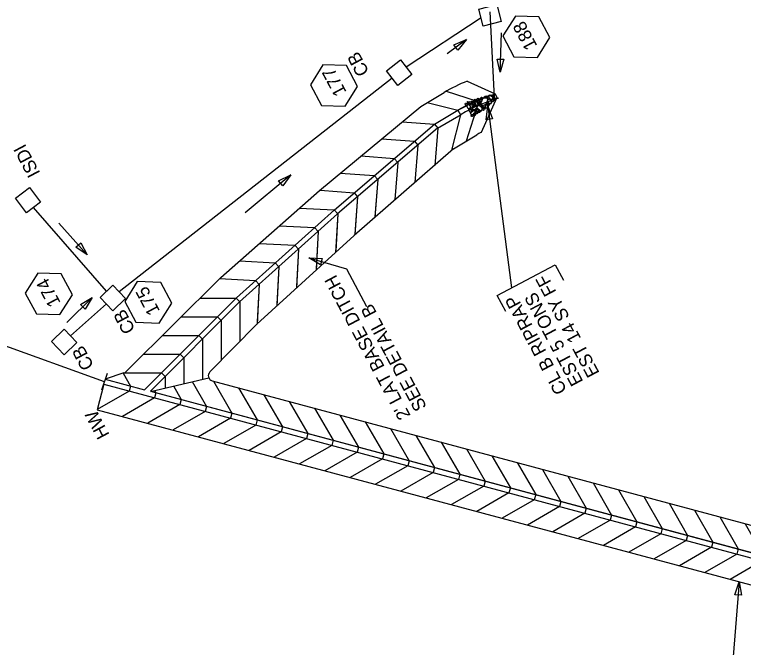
# Model space of a CAD drawing. Extents: x 2384780 to 2405432, y 547869 to 573706.
# Drawn here: x 2401953.5 to 2402230.7, y 571206.6 to 571447.5 of the extents above; entities that cross this region are included whole.
import ezdxf

# ---------------------------------------------------------------- set-up
doc = ezdxf.new("R2010")
doc.units = 0
for name, color, linetype in [('Old_Level_1', 7, 'Continuous'), ('Old_Level_18', 7, 'Continuous'), ('Old_Level_20', 7, 'Continuous'), ('Old_Level_5', 7, 'Continuous'), ('Old_Level_9', 7, 'Continuous'), ('Prop Drainage Structure Pipe RCP 36in', 7, 'Continuous')]:
    doc.layers.add(name, color=color, linetype=linetype)

# ---------------------------------------------------------------- blocks, each defined once
blk = doc.blocks.new('HDWL')
at = {"layer": 'Old_Level_1'}
for p, q in [((0, -0.0655), (0, 0.0685)), ((0, 0), (-0.0685, 0))]:
    blk.add_line(p, q, dxfattribs=at)

msp = doc.modelspace()

# ---------------------------------------------------------------- linework, layer by layer
at = {"layer": 'Old_Level_1'}
for p, q in [((2402136, 571416), (2402134.37, 571448.61)), ((2402130.92, 571446.33), (2402102.38, 571427.47)), ((2402097.07, 571423.39), (2401993.28, 571341.97)), ((2401988.43, 571342.2), (2401960.71, 571374.05)), ((2401988.46, 571337.38), (2401974.78, 571325.22)), ((2401994.99, 571311.1), (2401987.96, 571308.73)), ((2402005.13, 571304.12), (2402027.3, 571309.3)), ((2401987.44, 571306.8), (2401984.85, 571297.14))]:
    msp.add_line(p, q, dxfattribs=at)
for points in [[(2402131.92, 571415.92), (2402132.03, 571416.2), (2402132.4, 571416.54), (2402132.69, 571416.48), (2402132.79, 571416.28), (2402132.34, 571415.81), (2402132.11, 571415.81), (2402131.92, 571415.92)], [(2402132.65, 571415.95), (2402132.69, 571416.23), (2402133.07, 571416.57), (2402133.37, 571416.47), (2402133.46, 571416.31), (2402133.04, 571415.83), (2402132.8, 571415.82), (2402132.65, 571415.95)], [(2402133.61, 571416.29), (2402133.73, 571416.1), (2402133.95, 571415.71), (2402133.74, 571415.45), (2402133.58, 571415.37), (2402133.28, 571415.89), (2402133.33, 571416.26), (2402133.61, 571416.29)], [(2402134.24, 571417.02), (2402134.59, 571416.76), (2402135.34, 571416.05), (2402135.17, 571415.35), (2402134.68, 571415.13), (2402133.85, 571416.03), (2402133.83, 571416.68), (2402134.13, 571416.96)], [(2402135.68, 571415.94), (2402135.51, 571416.1), (2402135.07, 571416.42), (2402135.23, 571416.73), (2402135.4, 571416.82), (2402135.93, 571416.42), (2402135.94, 571416.09), (2402135.68, 571415.94)], [(2402125.16, 571413.86), (2402125.38, 571413.64), (2402125.65, 571413.23), (2402125.41, 571412.98), (2402125.14, 571412.91), (2402124.9, 571413.5), (2402124.98, 571413.8), (2402125.16, 571413.86)], [(2402126.12, 571413.62), (2402126.44, 571413.21), (2402126.94, 571412.38), (2402126.49, 571411.73), (2402125.96, 571411.69), (2402125.44, 571412.77), (2402125.66, 571413.37), (2402126.12, 571413.62)], [(2402125.97, 571414.48), (2402126.18, 571414.25), (2402126.46, 571413.85), (2402126.21, 571413.59), (2402125.95, 571413.52), (2402125.71, 571414.11), (2402125.79, 571414.41), (2402125.97, 571414.48)], [(2402126.65, 571414.49), (2402126.88, 571414.27), (2402127.16, 571413.86), (2402126.91, 571413.61), (2402126.65, 571413.54), (2402126.41, 571414.13), (2402126.49, 571414.43), (2402126.65, 571414.49)], [(2402127.07, 571414.07), (2402127.21, 571414.37), (2402127.57, 571414.73), (2402127.84, 571414.62), (2402127.92, 571414.47), (2402127.51, 571413.97), (2402127.26, 571413.96), (2402127.07, 571414.07)], [(2402127.38, 571413.43), (2402127.52, 571413.59), (2402127.85, 571414), (2402128.2, 571413.85), (2402128.28, 571413.68), (2402127.83, 571413.18), (2402127.59, 571413.29), (2402127.38, 571413.43)], [(2402128.44, 571413.8), (2402128.27, 571413.95), (2402127.94, 571414.33), (2402128.03, 571414.62), (2402128.15, 571414.7), (2402128.59, 571414.39), (2402128.63, 571414.07), (2402128.52, 571413.88)], [(2402128, 571412.97), (2402128.08, 571413.28), (2402128.45, 571413.61), (2402128.76, 571413.51), (2402128.82, 571413.33), (2402128.42, 571412.89), (2402128.19, 571412.85), (2402128, 571412.97)], [(2402128.29, 571414.72), (2402128.34, 571415), (2402128.71, 571415.34), (2402129.01, 571415.25), (2402129.1, 571415.08), (2402128.69, 571414.6), (2402128.44, 571414.59), (2402128.29, 571414.72)], [(2402129.33, 571414.88), (2402129.68, 571414.47), (2402130.09, 571413.54), (2402129.71, 571412.98), (2402129.17, 571412.88), (2402128.67, 571413.97), (2402128.85, 571414.68), (2402129.33, 571414.88)], [(2402129.28, 571415.04), (2402129.33, 571415.32), (2402129.7, 571415.66), (2402130, 571415.56), (2402130.09, 571415.4), (2402129.69, 571414.91), (2402129.43, 571414.9), (2402129.28, 571415.04)], [(2402130.18, 571414.21), (2402129.98, 571414.35), (2402129.57, 571414.68), (2402129.76, 571415.01), (2402129.9, 571415.08), (2402130.4, 571414.67), (2402130.4, 571414.45), (2402130.18, 571414.21)], [(2402130.13, 571413.78), (2402130.17, 571414.05), (2402130.57, 571414.36), (2402130.85, 571414.31), (2402130.96, 571414.12), (2402130.54, 571413.65), (2402130.29, 571413.65), (2402130.13, 571413.78)], [(2402130.39, 571415.63), (2402130.73, 571415.48), (2402131.23, 571414.98), (2402131.13, 571414.54), (2402130.86, 571414.4), (2402130.19, 571414.97), (2402130.18, 571415.4), (2402130.39, 571415.63)], [(2402130.65, 571413.49), (2402130.91, 571413.28), (2402131.01, 571412.87), (2402130.81, 571412.53), (2402130.59, 571412.55), (2402130.3, 571413.07), (2402130.49, 571413.4), (2402130.65, 571413.49)], [(2402131.1, 571416.14), (2402131.31, 571415.92), (2402131.59, 571415.51), (2402131.34, 571415.25), (2402131.08, 571415.19), (2402130.84, 571415.78), (2402130.92, 571416.08), (2402131.1, 571416.14)], [(2402130.91, 571413.31), (2402130.99, 571414.16), (2402131.72, 571415.74), (2402132.93, 571415.81), (2402133.52, 571415.24), (2402132.66, 571413.25), (2402131.75, 571412.88), (2402130.85, 571413.15)], [(2402132.93, 571413.86), (2402132.98, 571414.14), (2402133.36, 571414.47), (2402133.66, 571414.41), (2402133.72, 571414.22), (2402133.32, 571413.77), (2402133.12, 571413.75), (2402132.93, 571413.86)], [(2402132.96, 571413.27), (2402133.06, 571413.58), (2402133.44, 571413.86), (2402133.73, 571413.82), (2402133.84, 571413.62), (2402133.37, 571413.15), (2402133.15, 571413.16), (2402132.96, 571413.27)], [(2402134.05, 571415.51), (2402134.39, 571415.14), (2402134.89, 571414.25), (2402134.46, 571413.62), (2402134.01, 571413.59), (2402133.48, 571414.7), (2402133.65, 571415.26), (2402134.05, 571415.51)], [(2402134.71, 571414.64), (2402134.89, 571414.95), (2402135.3, 571415.43), (2402135.83, 571415.33), (2402136.03, 571414.99), (2402135.34, 571414.38), (2402134.98, 571414.4), (2402134.71, 571414.64)], [(2402136.28, 571415.12), (2402136.1, 571415.28), (2402135.64, 571415.63), (2402135.84, 571415.9), (2402136, 571416), (2402136.48, 571415.62), (2402136.54, 571415.27), (2402136.28, 571415.12)], [(2402126.72, 571411.72), (2402126.96, 571411.44), (2402127.27, 571410.88), (2402126.91, 571410.45), (2402126.62, 571410.38), (2402126.25, 571411.25), (2402126.41, 571411.6), (2402126.72, 571411.72)], [(2402127.46, 571412.14), (2402127.14, 571412.35), (2402126.68, 571412.92), (2402126.81, 571413.32), (2402127.07, 571413.46), (2402127.66, 571412.86), (2402127.75, 571412.48), (2402127.46, 571412.14)], [(2402128.63, 571410.61), (2402128.42, 571410.15), (2402127.71, 571409.4), (2402127.02, 571409.57), (2402126.87, 571410.09), (2402127.76, 571410.94), (2402128.25, 571410.99), (2402128.7, 571410.65)], [(2402127.16, 571410.95), (2402127.22, 571411.24), (2402127.59, 571411.59), (2402127.89, 571411.49), (2402127.98, 571411.33), (2402127.56, 571410.84), (2402127.32, 571410.82), (2402127.16, 571410.95)], [(2402129.36, 571412.43), (2402129.1, 571412.08), (2402128.35, 571411.32), (2402127.7, 571411.51), (2402127.44, 571411.96), (2402128.36, 571412.78), (2402128.96, 571412.94), (2402129.28, 571412.51)], [(2402128.7, 571411.2), (2402128.75, 571411.44), (2402129.15, 571411.85), (2402129.45, 571411.76), (2402129.51, 571411.57), (2402129.1, 571411.09), (2402128.9, 571411.06), (2402128.7, 571411.2)], [(2402129.6, 571411.44), (2402129.86, 571411.24), (2402129.96, 571410.82), (2402129.76, 571410.49), (2402129.54, 571410.5), (2402129.25, 571411.02), (2402129.44, 571411.35), (2402129.6, 571411.44)], [(2402130.72, 571410.93), (2402130.26, 571411.21), (2402129.33, 571411.95), (2402129.65, 571412.85), (2402130.07, 571413.09), (2402131.13, 571412.06), (2402131.22, 571411.3), (2402130.79, 571410.83)], [(2402129.86, 571410.3), (2402129.9, 571410.59), (2402130.28, 571410.92), (2402130.58, 571410.86), (2402130.64, 571410.67), (2402130.25, 571410.23), (2402130.06, 571410.2), (2402129.86, 571410.3)], [(2402131.23, 571412.19), (2402131.3, 571412.46), (2402131.68, 571412.76), (2402131.98, 571412.7), (2402132.08, 571412.51), (2402131.64, 571412.07), (2402131.42, 571412.08), (2402131.23, 571412.19)], [(2402131.85, 571411.08), (2402131.6, 571411.16), (2402131.29, 571411.46), (2402131.32, 571411.81), (2402131.6, 571411.98), (2402131.96, 571411.49), (2402132.01, 571411.18), (2402131.85, 571411.08)], [(2402131.85, 571411.66), (2402131.91, 571411.95), (2402132.29, 571412.28), (2402132.58, 571412.2), (2402132.64, 571412.02), (2402132.25, 571411.58), (2402132.05, 571411.55), (2402131.85, 571411.66)], [(2402132.95, 571413.24), (2402133.25, 571412.94), (2402133.54, 571412.42), (2402133.2, 571411.97), (2402132.86, 571411.95), (2402132.52, 571412.75), (2402132.7, 571413.1), (2402132.95, 571413.24)], [(2402133.36, 571412.83), (2402133.4, 571413.12), (2402133.78, 571413.45), (2402134.09, 571413.37), (2402134.14, 571413.19), (2402133.74, 571412.75), (2402133.54, 571412.71), (2402133.36, 571412.83)], [(2402127.14, 571408.84), (2402127.18, 571409.13), (2402127.56, 571409.46), (2402127.87, 571409.39), (2402127.92, 571409.2), (2402127.54, 571408.76), (2402127.33, 571408.73), (2402127.14, 571408.84)], [(2402128.44, 571410.09), (2402128.68, 571409.88), (2402128.79, 571409.46), (2402128.58, 571409.14), (2402128.36, 571409.15), (2402128.07, 571409.68), (2402128.28, 571410), (2402128.44, 571410.09)], [(2402129.46, 571409.74), (2402129.14, 571409.86), (2402128.86, 571410.21), (2402128.88, 571410.53), (2402129.14, 571410.69), (2402129.5, 571410.2), (2402129.59, 571409.9), (2402129.46, 571409.74)]]:
    msp.add_lwpolyline(points, dxfattribs=at)
for points in [[(2401990.85, 571334.8), (2401986.01, 571339.9), (2401990.86, 571344.51), (2401995.7, 571339.42)], [(2401972.35, 571318.06), (2401967.51, 571323.15), (2401972.36, 571327.76), (2401977.2, 571322.67)]]:
    msp.add_lwpolyline(points, close=True, dxfattribs=at)
at = {"layer": 'Old_Level_18'}
for p, q in [((2402107.93, 571412.59), (2402116.83, 571417.88)), ((2402113.16, 571405.83), (2402122.05, 571411.11)), ((2402114.38, 571404.24), (2402123.28, 571409.53)), ((2402120.38, 571396.47), (2402129.28, 571401.75)), ((2401995.44, 571311.15), (2401996.13, 571311.95)), ((2401987.96, 571308.73), (2402002.89, 571304.72)), ((2402028.63, 571308.17), (2402317.94, 571230.51)), ((2401987.44, 571306.8), (2402324.49, 571216.33)), ((2402005.1, 571304.13), (2402325, 571218.26)), ((2401984.85, 571297.14), (2402312.23, 571209.27))]:
    msp.add_line(p, q, dxfattribs=at)
for points in [[(2402117.58, 571418.32), (2402128.98, 571414.7), (2402128.98, 571414.7), (2402128.98, 571414.7), (2402129.7, 571413.31), (2402125.28, 571399.38)], [(2402122.05, 571411.11), (2402128.26, 571414.33), (2402134.79, 571416.81), (2402136.36, 571417.28)], [(2402110.42, 571414.07), (2402122.05, 571411.11), (2402122.05, 571411.11), (2402122.05, 571411.11), (2402123.11, 571409.33), (2402119.68, 571395.86)], [(2401996.13, 571311.95), (2402031.85, 571347.5), (2402069.49, 571380.57), (2402107.93, 571412.59)], [(2402113.16, 571405.83), (2402122.05, 571411.11)], [(2402002.89, 571304.72), (2402037.85, 571339.73), (2402075.12, 571373.27), (2402113.16, 571405.83)], [(2402100.94, 571406.77), (2402113.16, 571405.83), (2402113.16, 571405.83), (2402113.16, 571405.83), (2402114.46, 571404.3), (2402113.36, 571390.14)], [(2402114.38, 571404.24), (2402076.34, 571371.69), (2402039.07, 571338.14), (2402005.1, 571304.13)], [(2402093.12, 571400.26), (2402105.53, 571399.3), (2402105.53, 571399.3), (2402105.53, 571399.3), (2402106.83, 571397.77), (2402105.74, 571383.61)], [(2402120.38, 571396.47), (2402082.67, 571363.5), (2402045.64, 571329.64), (2402027.73, 571311.5)], [(2402085.3, 571393.74), (2402097.9, 571392.77), (2402097.9, 571392.77), (2402097.9, 571392.77), (2402099.21, 571391.24), (2402098.11, 571377.08)], [(2402077.48, 571387.23), (2402090.27, 571386.24), (2402090.27, 571386.24), (2402090.27, 571386.24), (2402091.58, 571384.71), (2402090.46, 571370.31)], [(2402077.48, 571387.23), (2402090.27, 571386.24), (2402090.27, 571386.24), (2402090.27, 571386.24), (2402091.58, 571384.71), (2402090.48, 571370.55)], [(2402069.66, 571380.71), (2402082.64, 571379.71), (2402082.64, 571379.71), (2402082.64, 571379.71), (2402083.95, 571378.18), (2402082.82, 571363.64)], [(2402069.66, 571380.71), (2402082.64, 571379.71), (2402082.64, 571379.71), (2402082.64, 571379.71), (2402083.95, 571378.18), (2402082.85, 571364.02)], [(2402061.86, 571373.87), (2402075.02, 571373.18), (2402075.02, 571373.18), (2402075.02, 571373.18), (2402076.36, 571371.68), (2402075.59, 571357.02)], [(2402061.86, 571373.87), (2402075.02, 571373.18), (2402075.02, 571373.18), (2402075.02, 571373.18), (2402076.36, 571371.68), (2402075.61, 571357.5)], [(2402054.23, 571367.16), (2402067.55, 571366.46), (2402067.55, 571366.46), (2402067.55, 571366.46), (2402068.9, 571364.96), (2402068.12, 571350.19)], [(2402054.23, 571367.16), (2402067.55, 571366.46), (2402067.55, 571366.46), (2402067.55, 571366.46), (2402068.9, 571364.96), (2402068.15, 571350.78)], [(2402046.59, 571360.45), (2402060.09, 571359.74), (2402060.09, 571359.74), (2402060.09, 571359.74), (2402061.43, 571358.25), (2402060.65, 571343.36)], [(2402046.59, 571360.45), (2402060.09, 571359.74), (2402060.09, 571359.74), (2402060.09, 571359.74), (2402061.43, 571358.25), (2402060.69, 571344.06)], [(2402038.96, 571353.74), (2402052.62, 571353.02), (2402052.62, 571353.02), (2402052.62, 571353.02), (2402053.97, 571351.53), (2402053.18, 571336.53)], [(2402038.96, 571353.74), (2402052.62, 571353.02), (2402052.62, 571353.02), (2402052.62, 571353.02), (2402053.97, 571351.53), (2402053.22, 571337.35)], [(2402031.38, 571347.03), (2402045.16, 571346.31), (2402045.16, 571346.31), (2402045.16, 571346.31), (2402046.51, 571344.81), (2402045.71, 571329.71)], [(2402031.38, 571347.03), (2402045.16, 571346.31), (2402045.16, 571346.31), (2402045.16, 571346.31), (2402046.51, 571344.81), (2402045.76, 571330.63)], [(2402023.89, 571339.57), (2402037.71, 571339.58), (2402037.71, 571339.58), (2402037.71, 571339.58), (2402039.13, 571338.16), (2402039.14, 571323.05)], [(2402023.89, 571339.57), (2402037.71, 571339.58), (2402037.71, 571339.58), (2402037.71, 571339.58), (2402039.13, 571338.16), (2402039.14, 571323.96)], [(2402016.75, 571332.47), (2402030.61, 571332.48), (2402030.61, 571332.48), (2402030.61, 571332.48), (2402032.03, 571331.05), (2402032.04, 571315.87)], [(2402016.75, 571332.47), (2402030.61, 571332.48), (2402030.61, 571332.48), (2402030.61, 571332.48), (2402032.03, 571331.05), (2402032.04, 571316.85)], [(2402009.61, 571325.36), (2402023.51, 571325.37), (2402023.51, 571325.37), (2402023.51, 571325.37), (2402024.94, 571323.95), (2402024.94, 571308.68)], [(2402009.61, 571325.36), (2402023.51, 571325.37), (2402023.51, 571325.37), (2402023.51, 571325.37), (2402024.94, 571323.95), (2402024.94, 571309.75)], [(2402002.47, 571318.26), (2402016.42, 571318.27), (2402016.42, 571318.27), (2402016.42, 571318.27), (2402017.84, 571316.85), (2402017.85, 571307.09)], [(2401994.77, 571311.03), (2401997.59, 571306.14), (2401997.59, 571306.14), (2401997.59, 571306.14), (2401997.07, 571304.22), (2401984.85, 571297.17)], [(2401995.12, 571311.15), (2402009.32, 571311.16), (2402009.32, 571311.16), (2402009.32, 571311.16), (2402010.74, 571309.74), (2402010.75, 571305.43)], [(2401987.96, 571308.73), (2402002.89, 571304.72)], [(2402013.86, 571306.16), (2402016.85, 571300.97), (2402016.85, 571300.97), (2402016.85, 571300.97), (2402016.33, 571299.05), (2402004.11, 571292)], [(2402021.03, 571307.84), (2402026.48, 571298.39), (2402026.48, 571298.39), (2402026.48, 571298.39), (2402025.96, 571296.46), (2402013.74, 571289.42)], [(2402029.06, 571308.02), (2402036.11, 571295.81), (2402036.11, 571295.81), (2402036.11, 571295.81), (2402035.59, 571293.88), (2402023.37, 571286.83)], [(2402038.69, 571305.44), (2402045.74, 571293.22), (2402045.74, 571293.22), (2402045.74, 571293.22), (2402045.22, 571291.29), (2402033, 571284.25)], [(2402006.68, 571304.48), (2402007.22, 571303.56), (2402007.22, 571303.56), (2402007.22, 571303.56), (2402006.7, 571301.63), (2401994.48, 571294.59)], [(2402005.1, 571304.13), (2402325, 571218.26)], [(2402048.32, 571302.85), (2402055.37, 571290.64), (2402055.37, 571290.64), (2402055.37, 571290.64), (2402054.85, 571288.71), (2402042.63, 571281.66)], [(2402057.95, 571300.27), (2402065, 571288.05), (2402065, 571288.05), (2402065, 571288.05), (2402064.48, 571286.12), (2402052.26, 571279.08)], [(2402067.58, 571297.68), (2402074.63, 571285.47), (2402074.63, 571285.47), (2402074.63, 571285.47), (2402074.11, 571283.54), (2402061.89, 571276.49)], [(2402077.21, 571295.1), (2402084.26, 571282.88), (2402084.26, 571282.88), (2402084.26, 571282.88), (2402083.74, 571280.95), (2402071.52, 571273.91)], [(2402086.84, 571292.51), (2402093.89, 571280.3), (2402093.89, 571280.3), (2402093.89, 571280.3), (2402093.37, 571278.37), (2402081.15, 571271.32)], [(2402096.47, 571289.93), (2402103.52, 571277.71), (2402103.52, 571277.71), (2402103.52, 571277.71), (2402103, 571275.78), (2402090.78, 571268.74)], [(2402106.1, 571287.34), (2402113.15, 571275.13), (2402113.15, 571275.13), (2402113.15, 571275.13), (2402112.63, 571273.2), (2402100.41, 571266.15)], [(2402115.73, 571284.76), (2402122.78, 571272.54), (2402122.78, 571272.54), (2402122.78, 571272.54), (2402122.26, 571270.61), (2402110.04, 571263.57)], [(2402125.36, 571282.17), (2402132.41, 571269.96), (2402132.41, 571269.96), (2402132.41, 571269.96), (2402131.89, 571268.03), (2402119.67, 571260.98)], [(2402134.99, 571279.59), (2402142.04, 571267.37), (2402142.04, 571267.37), (2402142.04, 571267.37), (2402141.52, 571265.44), (2402129.3, 571258.4)], [(2402144.62, 571277), (2402151.67, 571264.79), (2402151.67, 571264.79), (2402151.67, 571264.79), (2402151.15, 571262.86), (2402138.93, 571255.81)], [(2402154.25, 571274.42), (2402161.3, 571262.2), (2402161.3, 571262.2), (2402161.3, 571262.2), (2402160.78, 571260.28), (2402148.56, 571253.23)], [(2402163.88, 571271.83), (2402170.93, 571259.62), (2402170.93, 571259.62), (2402170.93, 571259.62), (2402170.41, 571257.69), (2402158.19, 571250.65)], [(2402173.51, 571269.25), (2402180.56, 571257.03), (2402180.56, 571257.03), (2402180.56, 571257.03), (2402180.04, 571255.11), (2402167.82, 571248.06)], [(2402183.14, 571266.66), (2402190.19, 571254.45), (2402190.19, 571254.45), (2402190.19, 571254.45), (2402189.67, 571252.52), (2402177.45, 571245.48)], [(2402192.77, 571264.08), (2402199.82, 571251.86), (2402199.82, 571251.86), (2402199.82, 571251.86), (2402199.3, 571249.94), (2402187.08, 571242.89)], [(2402202.4, 571261.49), (2402209.45, 571249.28), (2402209.45, 571249.28), (2402209.45, 571249.28), (2402208.93, 571247.35), (2402196.71, 571240.31)], [(2402212.03, 571258.91), (2402219.08, 571246.7), (2402219.08, 571246.7), (2402219.08, 571246.7), (2402218.56, 571244.77), (2402206.34, 571237.72)], [(2402221.66, 571256.33), (2402228.71, 571244.11), (2402228.71, 571244.11), (2402228.71, 571244.11), (2402228.19, 571242.18), (2402215.97, 571235.14)], [(2402231.29, 571253.74), (2402238.34, 571241.53), (2402238.34, 571241.53), (2402238.34, 571241.53), (2402237.82, 571239.6), (2402225.6, 571232.55)]]:
    msp.add_lwpolyline(points, dxfattribs=at)
for centre, radius, start, end in [((2402147.86, 571365.62), 60.78, 111.4459, 120.7011), ((2402153.08, 571358.85), 60.78, 105.9762, 120.7011), ((2402154.31, 571357.27), 60.78, 105.9762, 120.7011), ((2402160.31, 571349.5), 60.78, 118.9043, 120.7011), ((2402029.15, 571310.1), 2, 135.3618, 254.9754)]:
    msp.add_arc(centre, radius, start, end, dxfattribs=at)
at = {"layer": 'Old_Level_20'}
for points in [[(2402143.95, 571446.99), (2402139.21, 571439.4), (2402143.41, 571431.5), (2402152.36, 571431.19), (2402157.1, 571438.78), (2402152.9, 571446.68)], [(2402070.74, 571428.41), (2402066, 571420.82), (2402070.2, 571412.92), (2402079.15, 571412.61), (2402083.89, 571420.2), (2402079.69, 571428.1)]]:
    msp.add_lwpolyline(points, close=True, dxfattribs=at)
at = {"layer": 'Old_Level_5'}
for p, q in [((2402138.19, 571425.58), (2402138.63, 571440.6)), ((2402125.32, 571438.05), (2402118.01, 571432.53)), ((2402133.42, 571412.65), (2402142.46, 571343.49)), ((2402058.48, 571386.55), (2402041.21, 571372.04)), ((2401981.02, 571356.12), (2401970.28, 571368.13)), ((2402065.37, 571354.93), (2402079.65, 571350.81)), ((2402079.65, 571350.81), (2402087.31, 571336.42)), ((2401983.01, 571339.79), (2401973.33, 571330.29)), ((2402229.06, 571231.59), (2402224.52, 571175.91))]:
    msp.add_line(p, q, dxfattribs=at)
for points in [[(2402120.57, 571436.03), (2402125.32, 571438.05), (2402122.08, 571434.04)], [(2402139.58, 571430.54), (2402138.19, 571425.58), (2402137.08, 571430.62)], [(2402132.82, 571407.53), (2402133.42, 571412.65), (2402135.3, 571407.85)], [(2402053.85, 571384.29), (2402058.48, 571386.55), (2402055.45, 571382.38)], [(2401978.62, 571360.68), (2401981.02, 571356.12), (2401976.75, 571359.01)], [(2402069.77, 571352.25), (2402065.37, 571354.93), (2402070.51, 571354.63)], [(2401962.29, 571349.13), (2401957.54, 571341.54), (2401961.74, 571333.64), (2401970.69, 571333.32), (2401975.43, 571340.91), (2401971.23, 571348.81)], [(2402000.08, 571345.92), (2401995.34, 571338.33), (2401999.54, 571330.43), (2402008.48, 571330.12), (2402013.23, 571337.71), (2402009.03, 571345.61)], [(2401978.56, 571337.18), (2401983.01, 571339.79), (2401980.31, 571335.39)], [(2402227.4, 571226.71), (2402229.06, 571231.59), (2402229.9, 571226.51)]]:
    msp.add_lwpolyline(points, close=True, dxfattribs=at)
for points in [[(2402125.64, 571422.19), (2402136.32, 571417.39), (2402136.32, 571417.39), (2402136.32, 571417.39), (2402136.87, 571415.93), (2402130.93, 571402.7)], [(2402140.29, 571334.51), (2402137.05, 571340.61), (2402159.07, 571352.32), (2402162.2, 571346.44)]]:
    msp.add_lwpolyline(points, dxfattribs=at)
at = {"layer": 'Old_Level_9'}
for points in [[(2402138.55, 571444.84), (2402131.75, 571443.09), (2402130.08, 571449.58), (2402136.88, 571451.33)], [(2402099.21, 571420.6), (2402094.93, 571426.17), (2402100.24, 571430.26), (2402104.52, 571424.69)], [(2401958.04, 571372.03), (2401953.8, 571377.64), (2401959.15, 571381.68), (2401963.38, 571376.07)]]:
    msp.add_lwpolyline(points, close=True, dxfattribs=at)
at = {"layer": 'Prop Drainage Structure Pipe RCP 36in'}
msp.add_line((2401987.7, 571307.76), (2401819.24, 571368.62), dxfattribs=at)

# ---------------------------------------------------------------- block references
at = {"layer": 'Old_Level_5', "xscale": 50.00000000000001, "yscale": 50.000000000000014, "rotation": -18.16853840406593}
msp.add_blockref('HDWL', (2401987.7, 571307.76), dxfattribs=at)

# ---------------------------------------------------------------- texts
at = {"layer": 'Old_Level_20'}
for s, p in [('188', (2402152.4, 571435.66)), ('177', (2402079.84, 571418.06))]:
    msp.add_text(s, height=5, rotation=117.9999, dxfattribs=at).set_placement(p)
at = {"layer": 'Old_Level_5'}
for s, p in [('CB', (2402088.47, 571425.68)), ('ISDI', (2401963.34, 571387.19)), ('174', (2401971.11, 571337.85)), ("2' LAT BASE DITCH", (2402104.2, 571294.92)), ('EST 14 SY FF', (2402176.07, 571311.12)), ('175', (2402008.89, 571334.68)), ('EST 5 TONS', (2402169.89, 571307.83)), ('CL B RIPRAP', (2402163.71, 571304.54)), ('SEE DETAIL B', (2402110.38, 571298.21)), ('CB', (2401999.51, 571327.63)), ('CB', (2401983.77, 571313.8)), ('HW', (2401989.69, 571287.62))]:
    msp.add_text(s, height=5, rotation=117.9999, dxfattribs=at).set_placement(p)

doc.saveas('drawing.dxf')
